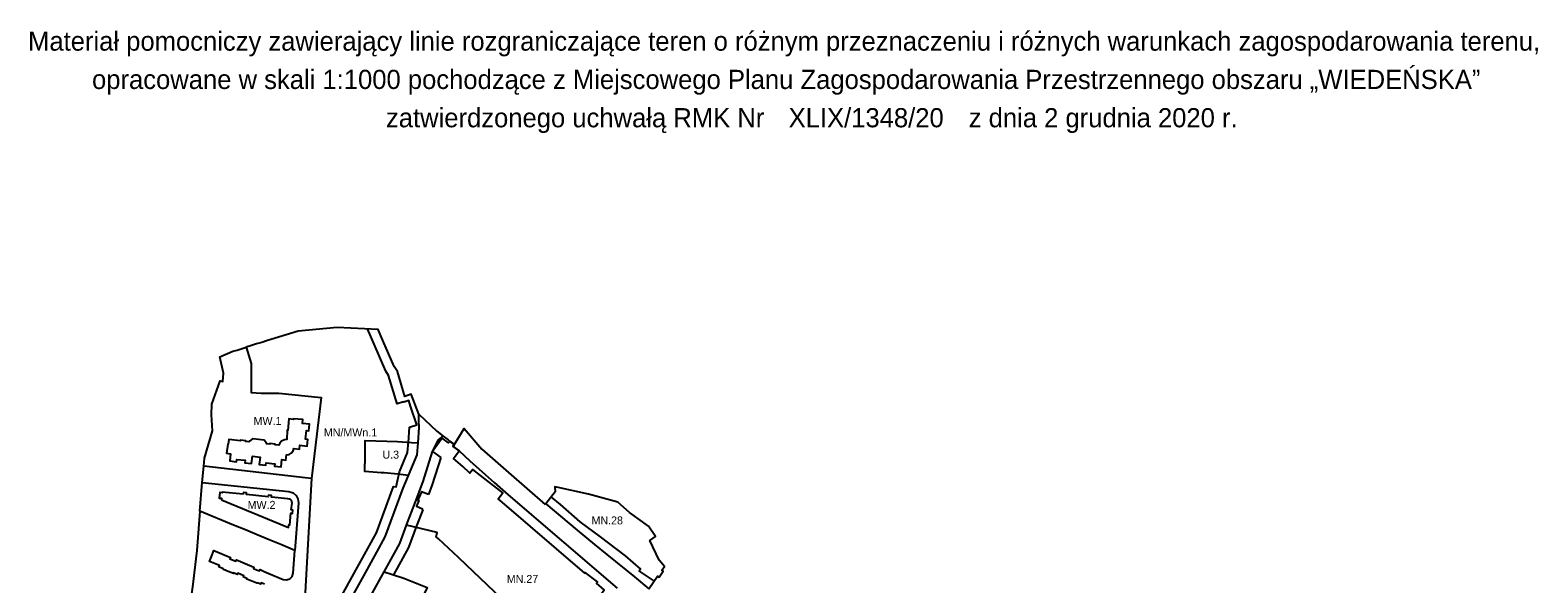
# Model space of a CAD drawing. Extents: x 7419601 to 7420547, y 5548907 to 5549873.
# Drawn here: x 7419601 to 7420547, y 5549527 to 5549873 of the extents above; entities that cross this region are included whole.
import ezdxf

# ---------------------------------------------------------------- set-up
doc = ezdxf.new("R2010")
doc.units = 0
for name, color, linetype in [('info', 7, 'Continuous'), ('LIN_linie_rozgraniczajace', 7, 'Continuous'), ('LIN_nieprzekraczalna linia zabudowy', 7, 'Continuous'), ('LIN_obowiązująca linia zabudowy', 7, 'Continuous'), ('TXT_opisy_przeznaczen', 7, 'Continuous')]:
    doc.layers.add(name, color=color, linetype=linetype)

msp = doc.modelspace()

# ---------------------------------------------------------------- linework, layer by layer
at = {"layer": 'LIN_linie_rozgraniczajace'}
for p, q in [((7419845.2, 5549632.9), (7419856.46, 5549622.18)), ((7419709.45, 5549590.16), (7419710.4, 5549600.3))]:
    msp.add_line(p, q, dxfattribs=at)
for points in [[(7419845.2, 5549632.9), (7419840.3, 5549645.31), (7419836.53, 5549644.02), (7419831.75, 5549659.55), (7419829.77, 5549662.67), (7419822.73, 5549679.06), (7419819.76, 5549685.97), (7419794.07, 5549687.19), (7419769.61, 5549684.97), (7419749.66, 5549678.78), (7419746.67, 5549677.85), (7419743.49, 5549676.87), (7419740.32, 5549675.88), (7419736.99, 5549674.85)], [(7419710.4, 5549600.3), (7419710.88, 5549605.34), (7419715.79, 5549622.4), (7419715.22, 5549632.36), (7419715.4, 5549639.19), (7419720.55, 5549653.79), (7419722.33, 5549653.42), (7419722.78, 5549658.57), (7419720.46, 5549668.84), (7419728.6, 5549672.27)], [(7419728.6, 5549672.27), (7419731.25, 5549673.08), (7419736.99, 5549674.85), (7419740.09, 5549664.63), (7419740.12, 5549646.53), (7419746.38, 5549646), (7419757.4, 5549646.01), (7419784.01, 5549643.32), (7419777.91, 5549592.55)], [(7419844.77, 5549614.88), (7419845.33, 5549624.45), (7419845.25, 5549628.71), (7419845.2, 5549632.9)], [(7419823.39, 5549534.11), (7419830, 5549545.78), (7419833.26, 5549551.75), (7419837.53, 5549563.26), (7419838.18, 5549565.02), (7419843.08, 5549577.88), (7419847.99, 5549590.75), (7419853.79, 5549609.47), (7419857.58, 5549616.77), (7419860.5, 5549619.1)], [(7419856.46, 5549622.18), (7419860.5, 5549619.1), (7419863.62, 5549616.72), (7419864.37, 5549615.86), (7419867.38, 5549613.68)], [(7419867.38, 5549613.68), (7419873.66, 5549623.94), (7419884.65, 5549610.93), (7419901.47, 5549596.23), (7419924.49, 5549576.19)], [(7419838.7, 5549594.38), (7419832.09, 5549595.31), (7419823.37, 5549596.02), (7419821.68, 5549596.16), (7419811.35, 5549596.99), (7419811.47, 5549606.7), (7419811.6, 5549616.42), (7419831.78, 5549615.78), (7419840.59, 5549615.21), (7419844.77, 5549614.88)], [(7419838.7, 5549594.38), (7419844.06, 5549607.32), (7419844.77, 5549614.88)], [(7419867.38, 5549613.68), (7419866.67, 5549612.69)], [(7419866.67, 5549612.69), (7419870.51, 5549609.89), (7419877.12, 5549603.54), (7419886.7, 5549595.06), (7419892.42, 5549590.02), (7419901.31, 5549582.26), (7419969.59, 5549523.82)], [(7419777.91, 5549592.55), (7419773.96, 5549592.99), (7419710.4, 5549600.3)], [(7419777.91, 5549592.55), (7419774.39, 5549528.85), (7419772.86, 5549501.2), (7419772.85, 5549500.98)], [(7419792.38, 5549498.69), (7419802.33, 5549516.61), (7419810.63, 5549531.56), (7419818.93, 5549546.5), (7419824.16, 5549555.93), (7419835.42, 5549586.49), (7419838.7, 5549594.38)], [(7419707.9, 5549572.09), (7419709.45, 5549590.16)], [(7419709.45, 5549590.16), (7419763.64, 5549584.36), (7419766.33, 5549583.52), (7419768.25, 5549581.94), (7419769.44, 5549579.77), (7419769.73, 5549577.3), (7419767.52, 5549547.51)], [(7419989.52, 5549523.43), (7419994.93, 5549531.32), (7419995.84, 5549530.7), (7419998.38, 5549534.49), (7419997.5, 5549535.08), (7419999.15, 5549537.48), (7419995.93, 5549541.49), (7419990.06, 5549553.81), (7419993.56, 5549556.15), (7419989.25, 5549562.64), (7419977.37, 5549571.35), (7419970.03, 5549577.66), (7419951.57, 5549582.76), (7419932.51, 5549586.98), (7419930.57, 5549587.41), (7419930.61, 5549584.15), (7419924.89, 5549576.71), (7419924.49, 5549576.19)], [(7419707.9, 5549572.09), (7419706.24, 5549550.17), (7419705.93, 5549547.4), (7419703.37, 5549524.79), (7419702.15, 5549517.49), (7419700.32, 5549509.31), (7419698.15, 5549496.9), (7419696.97, 5549490.2)], [(7419767.52, 5549547.51), (7419758.71, 5549551.15), (7419751.29, 5549554.2), (7419743.89, 5549557.27), (7419736.43, 5549560.33), (7419729.01, 5549563.39), (7419707.9, 5549572.09)], [(7419924.89, 5549576.71), (7419944.52, 5549560.18), (7419955.3, 5549551.19), (7419963.04, 5549544.9), (7419980.36, 5549530.97), (7419989.52, 5549523.43)], [(7419929.48, 5549492.2), (7419923.36, 5549496.34), (7419915.97, 5549502.3), (7419904.02, 5549511.77), (7419899.22, 5549515.43), (7419893.74, 5549520.56), (7419892.37, 5549521.85), (7419875.12, 5549538.31), (7419870.06, 5549543.14), (7419857.57, 5549554.7), (7419856.13, 5549556.04), (7419856.77, 5549558.74), (7419837.53, 5549563.26)], [(7419748.34, 5549526.35), (7419746.44, 5549527.14), (7419746.11, 5549526.35), (7419743.85, 5549527.29), (7419743.71, 5549526.96), (7419743.54, 5549527.03), (7419740.5, 5549528.29), (7419737.46, 5549529.53), (7419737.22, 5549529.63), (7419737.36, 5549529.96), (7419735.1, 5549530.9), (7419735.42, 5549531.68), (7419733.52, 5549532.47), (7419731.65, 5549533.24), (7419731.32, 5549532.46), (7419729.06, 5549533.39), (7419728.93, 5549533.05), (7419725.69, 5549534.39), (7419722.7, 5549535.63), (7419722.43, 5549535.74), (7419722.57, 5549536.07), (7419719.86, 5549537.18), (7419720.18, 5549537.96), (7419713.92, 5549540.55), (7419715.19, 5549543.6), (7419716.76, 5549547.42), (7419721.59, 5549545.38), (7419727.09, 5549543.11), (7419726.74, 5549542.34), (7419730.52, 5549540.78), (7419730.84, 5549541.57), (7419733.47, 5549540.48), (7419736.4, 5549539.28), (7419741.85, 5549537.03), (7419741.54, 5549536.24), (7419743.49, 5549535.43), (7419745.31, 5549534.69), (7419745.64, 5549535.47), (7419748.23, 5549534.37), (7419751.16, 5549533.12), (7419760.24, 5549529.34), (7419762.33, 5549529.01), (7419764.33, 5549529.66), (7419765.82, 5549531.16), (7419766.45, 5549533.16), (7419767.52, 5549547.51)], [(7419823.39, 5549534.11), (7419828.68, 5549532.39), (7419835.8, 5549530.09), (7419850.45, 5549524.3), (7419848.32, 5549519.98), (7419846.12, 5549517.67), (7419840.96, 5549502.57), (7419827.22, 5549508.13), (7419815.32, 5549513.23), (7419812.9, 5549514.98)], [(7419812.9, 5549514.98), (7419821.49, 5549530.74), (7419823.39, 5549534.11)]]:
    msp.add_lwpolyline(points, dxfattribs=at)
at = {"layer": 'LIN_nieprzekraczalna linia zabudowy'}
for points in [[(7419787.11, 5549501.56), (7419818.69, 5549558.44), (7419829.41, 5549587.53), (7419831.09, 5549587.37), (7419833.15, 5549596.68), (7419838.17, 5549608.78), (7419838.8, 5549615.45), (7419838.78, 5549615.23), (7419839.34, 5549624.76), (7419839.32, 5549624.76), (7419843.92, 5549626.29), (7419840.06, 5549637.87), (7419838.86, 5549641.47), (7419835.73, 5549640.43), (7419835.64, 5549640.71), (7419831.66, 5549639.43), (7419826.25, 5549657.02), (7419824.45, 5549659.86), (7419817.22, 5549676.69), (7419813.09, 5549686.29)], [(7419870.51, 5549609.89), (7419866.43, 5549612.86), (7419867.29, 5549614.06), (7419864.76, 5549615.93), (7419863.91, 5549614.85), (7419859.81, 5549617.78), (7419853.79, 5549609.47), (7419858.91, 5549605.72)], [(7419917.85, 5549487.33), (7419918.78, 5549488.99), (7419928.33, 5549500.05), (7419939.1, 5549493.19), (7419941.66, 5549496.31), (7419961.43, 5549522.9), (7419956.67, 5549526.98), (7419957.33, 5549527.78), (7419949.59, 5549533.78), (7419949.24, 5549533.34), (7419897.39, 5549577.72), (7419894.99, 5549579.82), (7419897.92, 5549583.55), (7419883.95, 5549594.54), (7419879.16, 5549598.29), (7419877.23, 5549595.94), (7419877.05, 5549596.11), (7419872.74, 5549600.12), (7419866.91, 5549605.07), (7419870.51, 5549609.89)], [(7419858.91, 5549605.72), (7419853.66, 5549588.79), (7419851.25, 5549582.46)], [(7419851.25, 5549582.46), (7419846.97, 5549584.32), (7419844.65, 5549579.02), (7419845.16, 5549578.8), (7419843.71, 5549575.34), (7419847.5, 5549573.65), (7419847.24, 5549573.07), (7419847.61, 5549572.92)], [(7419847.61, 5549572.92), (7419843.8, 5549562.91), (7419838.74, 5549549.25), (7419835.25, 5549542.86), (7419829.22, 5549532.22)], [(7419928.15, 5549580.95), (7419933.74, 5549576.29), (7419946.09, 5549565.39), (7419958.88, 5549556), (7419974.66, 5549544.11), (7419984.24, 5549535.7), (7419983.39, 5549534.41), (7419992.76, 5549528.15)]]:
    msp.add_lwpolyline(points, dxfattribs=at)
at = {"layer": 'LIN_obowiązująca linia zabudowy'}
for points in [[(7419741.16, 5549617.43), (7419740.89, 5549617.46), (7419739, 5549616.06), (7419738.74, 5549615.87), (7419738.71, 5549615.58), (7419736.71, 5549615.81), (7419736.74, 5549616.16), (7419733.39, 5549616.55), (7419733.35, 5549616.19), (7419726.1, 5549617.08), (7419725.75, 5549614.06), (7419725.41, 5549614.11), (7419724.71, 5549608.38), (7419727.18, 5549608.09), (7419726.65, 5549603.56), (7419730.84, 5549603.08), (7419731.01, 5549604.58), (7419736.31, 5549603.97), (7419736.14, 5549602.48), (7419740.34, 5549601.99), (7419740.86, 5549606.48), (7419745.65, 5549605.94), (7419745.13, 5549601.44), (7419749.25, 5549600.97), (7419749.42, 5549602.43), (7419754.85, 5549601.81), (7419754.68, 5549600.34), (7419758.82, 5549599.86), (7419759.34, 5549604.44), (7419761.82, 5549604.14), (7419762.2, 5549607.43), (7419763.84, 5549607.7), (7419765.19, 5549608.5), (7419766.4, 5549609.83), (7419766.9, 5549611.29), (7419770.31, 5549610.9), (7419770.57, 5549613.38), (7419775.14, 5549612.82), (7419775.66, 5549617.03), (7419774.16, 5549617.21), (7419774.82, 5549622.55), (7419776.31, 5549622.36), (7419776.72, 5549626.53), (7419772.19, 5549626.98), (7419772.43, 5549629.44), (7419766.68, 5549630.01), (7419766.65, 5549629.64), (7419763.69, 5549629.93), (7419762.98, 5549622.74), (7419762.63, 5549622.78), (7419762.41, 5549617.06), (7419760.9, 5549616.79), (7419759.19, 5549616.06), (7419758.12, 5549614.79), (7419757.45, 5549613.42), (7419755.19, 5549613.68), (7419755.22, 5549614.06), (7419751.87, 5549614.41), (7419751.84, 5549614.06), (7419749.75, 5549614.31), (7419749.78, 5549614.61), (7419748.19, 5549616.63)], [(7419721.44, 5549579.14), (7419763.58, 5549561.88), (7419763.77, 5549563.63), (7419764.28, 5549563.57), (7419765.02, 5549570.78), (7419766.03, 5549570.68), (7419766.25, 5549572.8), (7419765.25, 5549572.89), (7419765.69, 5549577.2), (7419765.6, 5549577.88), (7419765.27, 5549578.73), (7419764.7, 5549579.32), (7419764.01, 5549579.69), (7419763, 5549579.81), (7419752.78, 5549580.85), (7419752.88, 5549581.88), (7419750.91, 5549582.09), (7419750.81, 5549581.07), (7419737.07, 5549582.48), (7419737.18, 5549583.55), (7419735.19, 5549583.75), (7419735.08, 5549582.69), (7419721.95, 5549584.04), (7419721.9, 5549583.58), (7419720.37, 5549583.73), (7419720.01, 5549580.34), (7419721.55, 5549580.18)]]:
    msp.add_lwpolyline(points, close=True, dxfattribs=at)

# ---------------------------------------------------------------- texts
at = {"layer": 'info'}
for s, p in [('Materiał pomocniczy zawierający linie rozgraniczające teren o różnym przeznaczeniu i różnych warunkach zagospodarowania terenu, ', (7419600.18, 5549860.62)), ('opracowane w skali 1:1000 pochodzące z Miejscowego Planu Zagospodarowania Przestrzennego obszaru „WIEDEŃSKA” ', (7419640.29, 5549836.62)), ('zatwierdzonego uchwałą RMK Nr ', (7419824.59, 5549812.62)), ('XLIX/1348/20  ', (7420077.07, 5549812.62)), ('z dnia 2 grudnia 2020 r.', (7420190.01, 5549812.62))]:
    msp.add_text(s, height=12, dxfattribs=at).set_placement(p)
at = {"layer": 'TXT_opisy_przeznaczen'}
for s, p in [('MW.1', (7419741.59, 5549626.12)), ('MN/MWn.1', (7419785.65, 5549618.91)), ('U.3', (7419822.41, 5549605.02)), ('MW.2', (7419737.86, 5549573.54)), ('MN.28', (7419953.5, 5549563.82)), ('MN.27', (7419900.37, 5549527.15))]:
    msp.add_text(s, height=5, dxfattribs=at).set_placement(p)

doc.saveas('drawing.dxf')
